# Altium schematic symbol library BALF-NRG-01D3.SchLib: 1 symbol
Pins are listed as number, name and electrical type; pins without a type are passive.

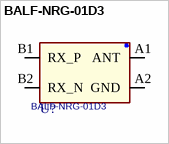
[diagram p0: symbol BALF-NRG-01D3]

## BALF-NRG-01D3
designator U?
footprint ST_CSP04N40P2X2_88X143X68
pins: A1 ANT, A2 GND, B1 RX_P, B2 RX_N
